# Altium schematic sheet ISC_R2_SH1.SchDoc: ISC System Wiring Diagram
size C; DrawnBy: Filiberto Clara; Engineer: Filiberto Clara; Organization: LIGO Laboratory; Address1: California Institute of Technology; Address2: Massachusetts Institute of Technology; SheetNumber: 13; SheetTotal: 39
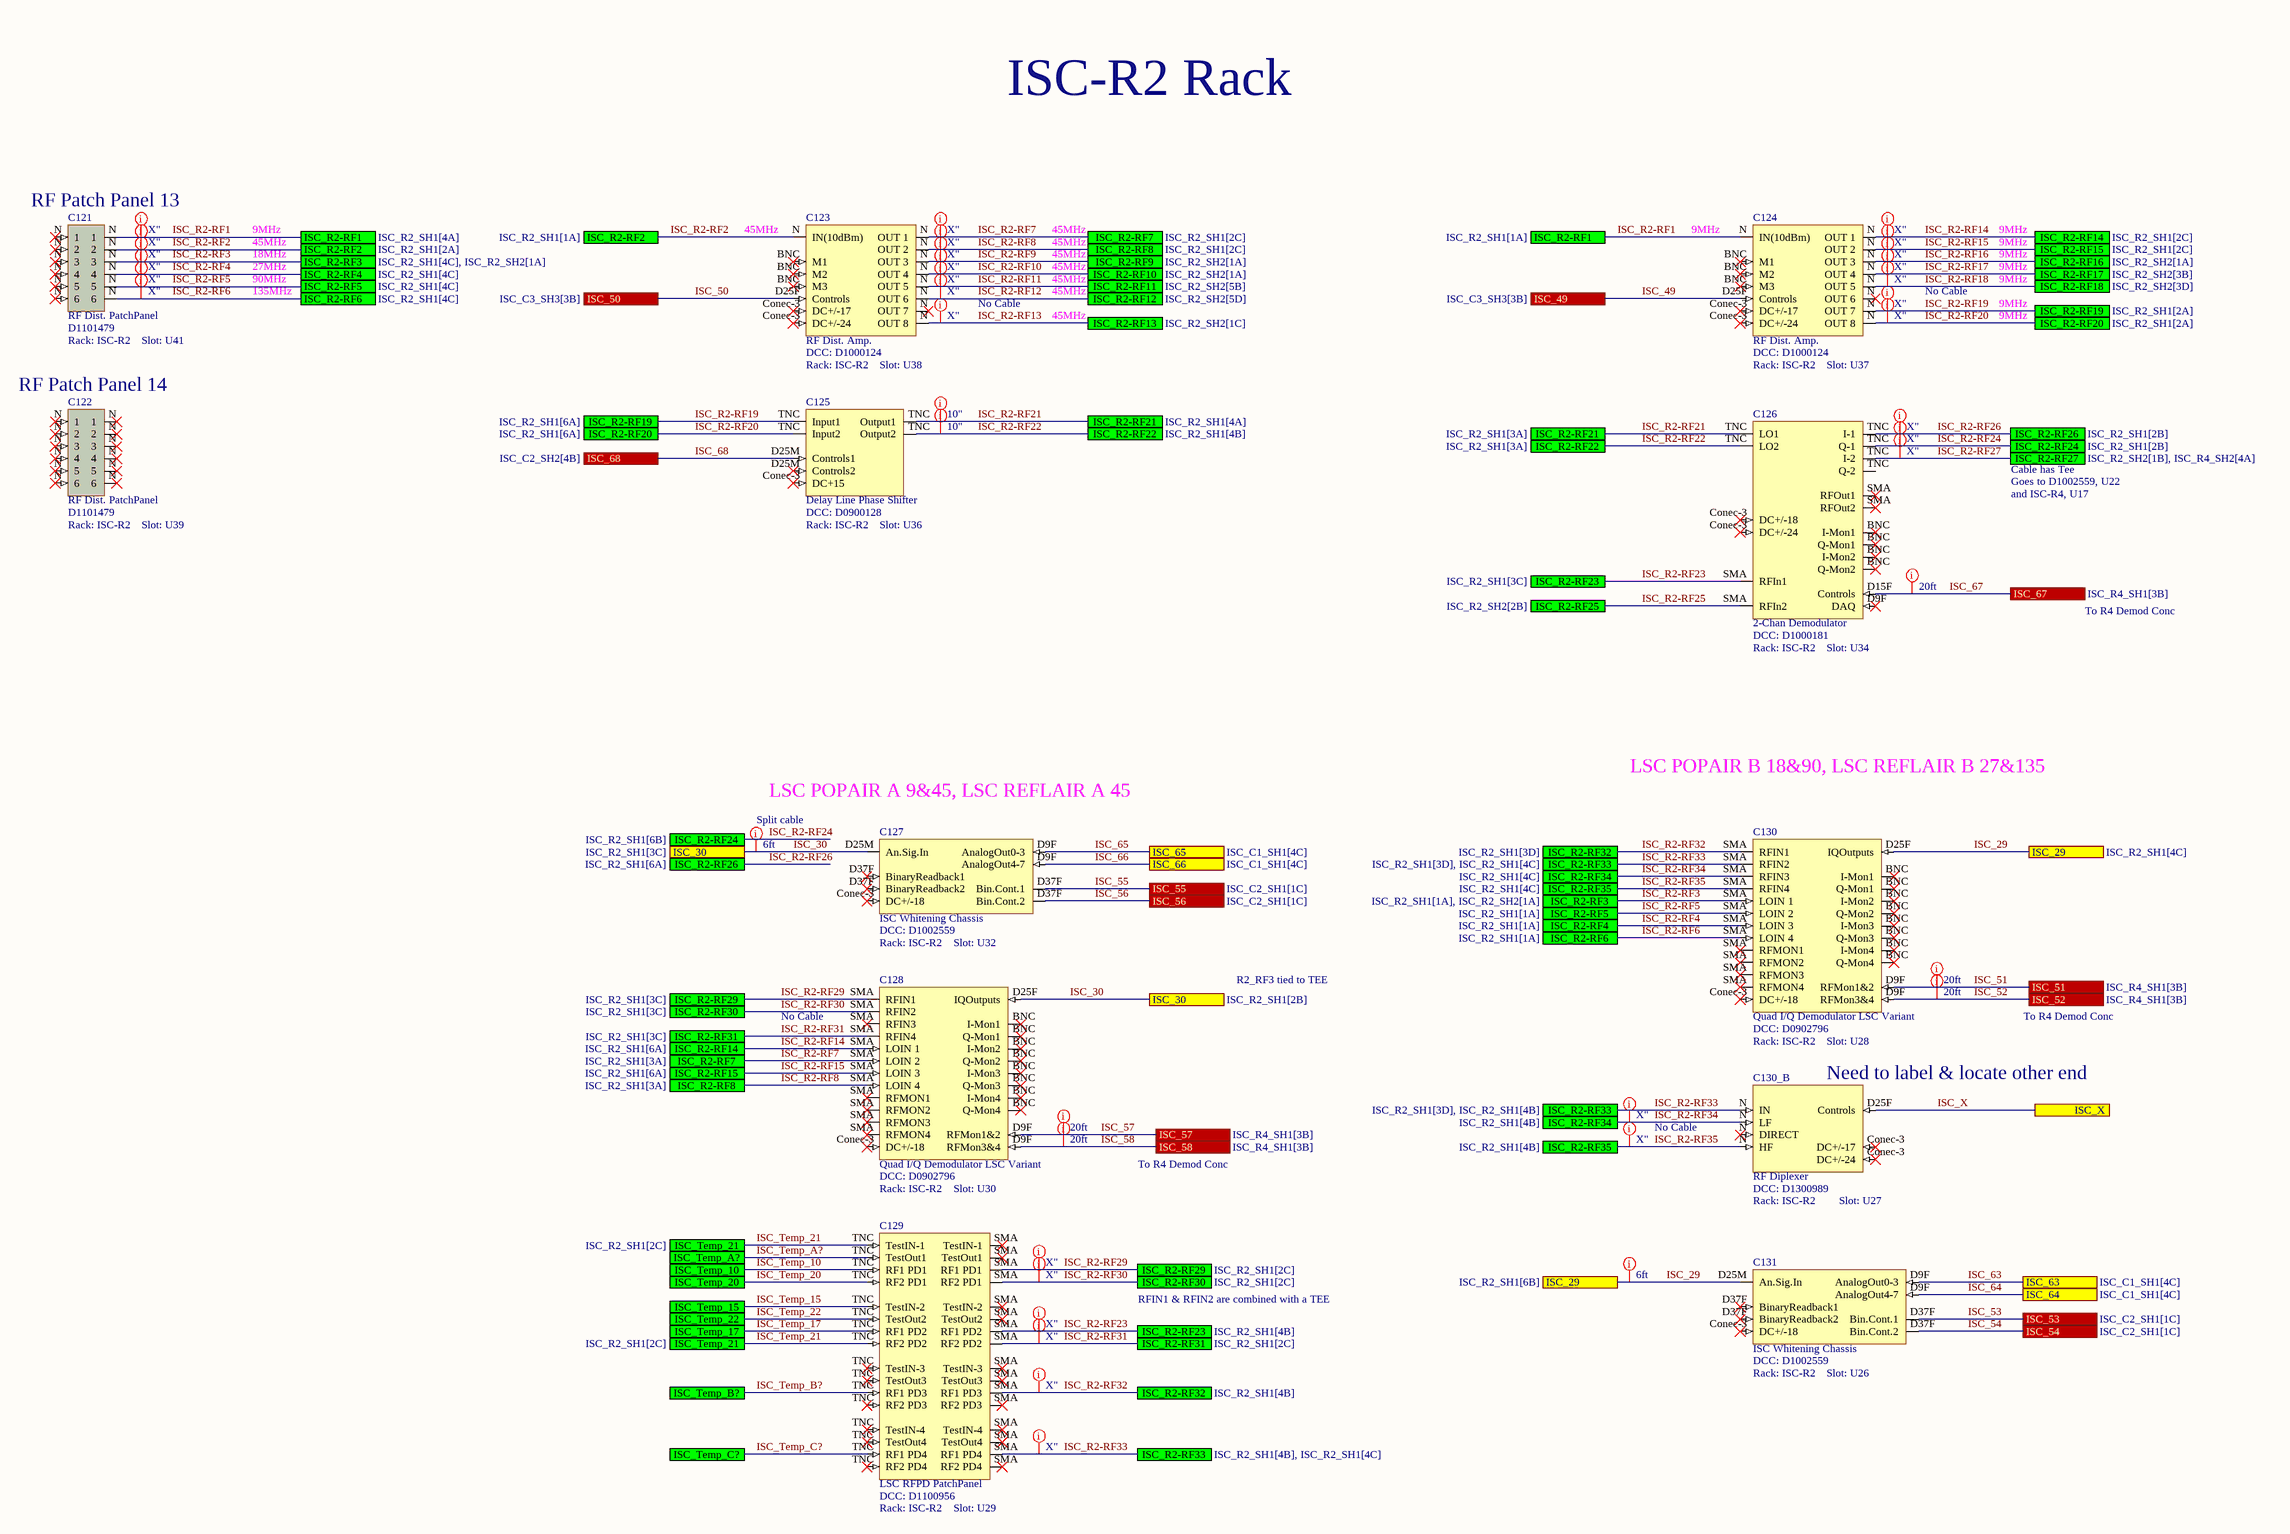
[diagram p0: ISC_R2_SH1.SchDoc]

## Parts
C121  RF Dist. PatchPanel  DCC: D1101479  Rack: ISC-R2  Slot: U41
C122  RF Dist. PatchPanel  DCC: D1101479  Rack: ISC-R2  Slot: U39
C123  RF Dist. Amp.  DCC: D1000124  Rack: ISC-R2  Slot: U38
C124  RF Dist. Amp.  DCC: D1000124  Rack: ISC-R2  Slot: U37
C125  Delay Line Phase Shifter  DCC: D0900128  Rack: ISC-R2  Slot: U36
C126  2-Chan Demodulator  DCC: D1000181  Rack: ISC-R2  Slot: U34
C127  ISC Whitening Chassis  DCC: D1002559  Rack: ISC-R2  Slot: U32
C128  Quad I/Q Demodulator LSC Variant  DCC: D0902796  Rack: ISC-R2  Slot: U30
C129  LSC RFPD PatchPanel  DCC: D1100956  Rack: ISC-R2  Slot: U29
C130  Quad I/Q Demodulator LSC Variant  DCC: D0902796  Rack: ISC-R2  Slot: U28
C130_B  RF Diplexer  DCC: D1300989  Rack: ISC-R2  Slot: U27
C131  ISC Whitening Chassis  DCC: D1002559  Rack: ISC-R2  Slot: U26

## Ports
ISC_29 (see ISC_R2_SH1[4C]), ISC_29 (see ISC_R2_SH1[6B]), ISC_30 (see ISC_R2_SH1[2B]), ISC_30 (see ISC_R2_SH1[3C]), ISC_49 (see ISC_C3_SH3[3B]), ISC_50 (see ISC_C3_SH3[3B]), ISC_51 (see ISC_R4_SH1[3B]), ISC_52 (see ISC_R4_SH1[3B]), ISC_53 (see ISC_C2_SH1[1C]), ISC_54 (see ISC_C2_SH1[1C]), ISC_55 (see ISC_C2_SH1[1C]), ISC_56 (see ISC_C2_SH1[1C]), ISC_57 (see ISC_R4_SH1[3B]), ISC_58 (see ISC_R4_SH1[3B]), ISC_63 (see ISC_C1_SH1[4C]), ISC_64 (see ISC_C1_SH1[4C]), ISC_65 (see ISC_C1_SH1[4C]), ISC_66 (see ISC_C1_SH1[4C]), ISC_67 (see ISC_R4_SH1[3B]), ISC_68 (see ISC_C2_SH2[4B]), ISC_R2-RF1 (see ISC_R2_SH1[1A]), ISC_R2-RF1 (see ISC_R2_SH1[4A]), ISC_R2-RF2 (see ISC_R2_SH1[1A]), ISC_R2-RF2 (see ISC_R2_SH1[2A]), ISC_R2-RF3 (see ISC_R2_SH1[1A], ISC_R2_SH2[1A]), ISC_R2-RF3 (see ISC_R2_SH1[4C], ISC_R2_SH2[1A]), ISC_R2-RF4 (see ISC_R2_SH1[1A]), ISC_R2-RF4 (see ISC_R2_SH1[4C]), ISC_R2-RF5 (see ISC_R2_SH1[1A]), ISC_R2-RF5 (see ISC_R2_SH1[4C]), ISC_R2-RF6 (see ISC_R2_SH1[1A]), ISC_R2-RF6 (see ISC_R2_SH1[4C]), ISC_R2-RF7 (see ISC_R2_SH1[2C]), ISC_R2-RF7 (see ISC_R2_SH1[3A]), ISC_R2-RF8 (see ISC_R2_SH1[2C]), ISC_R2-RF8 (see ISC_R2_SH1[3A]), ISC_R2-RF9 (see ISC_R2_SH2[1A]), ISC_R2-RF10 (see ISC_R2_SH2[1A]), ISC_R2-RF11 (see ISC_R2_SH2[5B]), ISC_R2-RF12 (see ISC_R2_SH2[5D]), ISC_R2-RF13 (see ISC_R2_SH2[1C]), ISC_R2-RF14 (see ISC_R2_SH1[2C]), ISC_R2-RF14 (see ISC_R2_SH1[6A]), ISC_R2-RF15 (see ISC_R2_SH1[2C]), ISC_R2-RF15 (see ISC_R2_SH1[6A]), ISC_R2-RF16 (see ISC_R2_SH2[1A]), ISC_R2-RF17 (see ISC_R2_SH2[3B]), ISC_R2-RF18 (see ISC_R2_SH2[3D]), ISC_R2-RF19 (see ISC_R2_SH1[2A]), ISC_R2-RF19 (see ISC_R2_SH1[6A]), ISC_R2-RF20 (see ISC_R2_SH1[2A]), ISC_R2-RF20 (see ISC_R2_SH1[6A]), ISC_R2-RF21 (see ISC_R2_SH1[3A]), ISC_R2-RF21 (see ISC_R2_SH1[4A]), ISC_R2-RF22 (see ISC_R2_SH1[3A]), ISC_R2-RF22 (see ISC_R2_SH1[4B]), ISC_R2-RF23 (see ISC_R2_SH1[3C]), ISC_R2-RF23 (see ISC_R2_SH1[4B]), ISC_R2-RF24 (see ISC_R2_SH1[2B]), ISC_R2-RF24 (see ISC_R2_SH1[6B]), ISC_R2-RF25 (see ISC_R2_SH2[2B]), ISC_R2-RF26 (see ISC_R2_SH1[2B]), ISC_R2-RF26 (see ISC_R2_SH1[6A]), ISC_R2-RF27 (see ISC_R2_SH2[1B], ISC_R4_SH2[4A]), ISC_R2-RF29 (see ISC_R2_SH1[2C]), ISC_R2-RF29 (see ISC_R2_SH1[3C]), ISC_R2-RF30 (see ISC_R2_SH1[2C]), ISC_R2-RF30 (see ISC_R2_SH1[3C]), ISC_R2-RF31 (see ISC_R2_SH1[2C]), ISC_R2-RF31 (see ISC_R2_SH1[3C]), ISC_R2-RF32 (see ISC_R2_SH1[3D]), ISC_R2-RF32 (see ISC_R2_SH1[4B]), ISC_R2-RF33 (see ISC_R2_SH1[3D], ISC_R2_SH1[4B]), ISC_R2-RF33 (see ISC_R2_SH1[3D], ISC_R2_SH1[4C]), ISC_R2-RF33 (see ISC_R2_SH1[4B], ISC_R2_SH1[4C]), ISC_R2-RF34 (see ISC_R2_SH1[4B]), ISC_R2-RF34 (see ISC_R2_SH1[4C]), ISC_R2-RF35 (see ISC_R2_SH1[4B]), ISC_R2-RF35 (see ISC_R2_SH1[4C]), ISC_Temp_10, ISC_Temp_15, ISC_Temp_17, ISC_Temp_20, ISC_Temp_21 (see ISC_R2_SH1[2C]), ISC_Temp_22, ISC_Temp_A?, ISC_Temp_B?, ISC_Temp_C?, ISC_X

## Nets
ISC_29: C130.D25F(IQOutputs) C131.D25M(An.Sig.In) ; port ISC_29
ISC_30: C127.D25M(An.Sig.In) C128.D25F(IQOutputs) ; port ISC_30
ISC_49: C124.D25F(Controls) ; port ISC_49
ISC_50: C123.D25F(Controls) ; port ISC_50
ISC_51: C130.D9F(RFMon1&2) ; port ISC_51
ISC_52: C130.D9F(RFMon3&4) ; port ISC_52
ISC_53: C131.D37F(BinaryReadback1) ; port ISC_53
ISC_54: C131.D37F(Bin.Cont.2) ; port ISC_54
ISC_55: C127.D37F(BinaryReadback1) ; port ISC_55
ISC_56: C127.D37F(Bin.Cont.2) ; port ISC_56
ISC_57: C128.D9F(RFMon1&2) ; port ISC_57
ISC_58: C128.D9F(RFMon3&4) ; port ISC_58
ISC_63: C131.D9F(AnalogOut0-3) ; port ISC_63
ISC_64: C131.D9F(AnalogOut4-7) ; port ISC_64
ISC_65: C127.D9F(AnalogOut0-3) ; port ISC_65
ISC_66: C127.D9F(AnalogOut4-7) ; port ISC_66
ISC_67: C126.D15F(Controls) ; port ISC_67
ISC_68: C125.D25M(Controls1) ; port ISC_68
ISC_R2-RF1: C121.N(1) C124.N(IN(10dBm)) ; port ISC_R2-RF1
ISC_R2-RF2: C121.N(2) C123.N(IN(10dBm)) ; port ISC_R2-RF2
ISC_R2-RF3: C121.N(3) C130.SMA(LOIN_1) ; port ISC_R2-RF3
ISC_R2-RF4: C121.N(4) C130.SMA(LOIN_3) ; port ISC_R2-RF4
ISC_R2-RF5: C121.N(5) C130.SMA(LOIN_2) ; port ISC_R2-RF5
ISC_R2-RF6: C121.N(6) C130.SMA(LOIN_4) ; port ISC_R2-RF6
ISC_R2-RF7: C123.N(OUT_1) C128.SMA(LOIN_2) ; port ISC_R2-RF7
ISC_R2-RF8: C123.N(OUT_2) C128.SMA(LOIN_4) ; port ISC_R2-RF8
ISC_R2-RF9: C123.N(OUT_3) ; port ISC_R2-RF9
ISC_R2-RF10: C123.N(OUT_4) ; port ISC_R2-RF10
ISC_R2-RF11: C123.N(OUT_5) ; port ISC_R2-RF11
ISC_R2-RF12: C123.N(OUT_6) ; port ISC_R2-RF12
ISC_R2-RF13: C123.N(OUT_8) ; port ISC_R2-RF13
ISC_R2-RF14: C124.N(OUT_1) C128.SMA(LOIN_1) ; port ISC_R2-RF14
ISC_R2-RF15: C124.N(OUT_2) C128.SMA(LOIN_3) ; port ISC_R2-RF15
ISC_R2-RF16: C124.N(OUT_3) ; port ISC_R2-RF16
ISC_R2-RF17: C124.N(OUT_4) ; port ISC_R2-RF17
ISC_R2-RF18: C124.N(OUT_5) ; port ISC_R2-RF18
ISC_R2-RF19: C124.N(OUT_7) C125.TNC(Input1) ; port ISC_R2-RF19
ISC_R2-RF20: C124.N(OUT_8) C125.TNC(Input2) ; port ISC_R2-RF20
ISC_R2-RF21: C125.TNC(Output1) C126.TNC(LO1) ; port ISC_R2-RF21
ISC_R2-RF22: C125.TNC(Output2) C126.TNC(LO2) ; port ISC_R2-RF22
ISC_R2-RF23: C126.SMA(RFOut1) C129.SMA(RF1_PD2) ; port ISC_R2-RF23
ISC_R2-RF24: C126.TNC(Q-1) ; port ISC_R2-RF24
ISC_R2-RF25: C126.SMA(RFIn2) ; port ISC_R2-RF25
ISC_R2-RF26: C126.TNC(I-1) ; port ISC_R2-RF26
ISC_R2-RF27: C126.TNC(I-2) ; port ISC_R2-RF27
ISC_R2-RF29: C128.SMA(RFIN1) C129.SMA(TestIN-1) ; port ISC_R2-RF29
ISC_R2-RF30: C128.SMA(RFIN2) C129.SMA(RF2_PD1) ; port ISC_R2-RF30
ISC_R2-RF31: C128.SMA(RFIN4) C129.SMA(RF2_PD2) ; port ISC_R2-RF31
ISC_R2-RF32: C129.SMA(RF1_PD3) C130.SMA(RFIN1) ; port ISC_R2-RF32
ISC_R2-RF33: C129.SMA(RF1_PD4) C130.SMA(RFIN2) C130_B.N(IN) ; port ISC_R2-RF33
ISC_R2-RF34: C130.SMA(RFIN3) C130_B.N(LF) ; port ISC_R2-RF34
ISC_R2-RF35: C130.SMA(RFIN4) C130_B.N(HF) ; port ISC_R2-RF35
ISC_Temp_10: C129.TNC(RF1_PD1) ; port ISC_Temp_10
ISC_Temp_15: C129.TNC(TestIN-2) ; port ISC_Temp_15
ISC_Temp_17: C129.TNC(RF1_PD2) ; port ISC_Temp_17
ISC_Temp_20: C129.TNC(RF2_PD1) ; port ISC_Temp_20
ISC_Temp_21: C129.TNC(TestIN-1) ; port ISC_Temp_21
ISC_Temp_22: C129.TNC(TestOut2) ; port ISC_Temp_22
ISC_Temp_A?: C129.TNC(TestOut1) ; port ISC_Temp_A?
ISC_Temp_B?: C129.TNC(RF1_PD3) ; port ISC_Temp_B?
ISC_Temp_C?: C129.TNC(RF1_PD4) ; port ISC_Temp_C?
ISC_X: C130_B.D25F(Controls) ; port ISC_X

Not connected (* = marked no-connect by the designer): C122 N(1)*; C123 BNC(M1)* Conec-3(DC+/-17)*; C124 BNC(M1)* Conec-3(DC+/-17)*; C125 Conec-3(DC+15)*; C126 BNC(I-Mon1)* Conec-3(DC+/-18)* D9F(DAQ)*; C127 Conec-3(DC+/-18)*; C128 BNC(I-Mon1)* Conec-3(DC+/-18)*; C130 BNC(I-Mon1)* Conec-3(DC+/-18)*; C130_B Conec-3(DC+/-17)*; C131 Conec-3(DC+/-18)*

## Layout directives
Length: X": ISC_R2-RF1, ISC_R2-RF2, ISC_R2-RF3, ISC_R2-RF4, ISC_R2-RF5, ISC_R2-RF6, ISC_R2-RF7, ISC_R2-RF8, ISC_R2-RF9, ISC_R2-RF10, ISC_R2-RF11, ISC_R2-RF12, ISC_R2-RF13, ISC_R2-RF14, ISC_R2-RF15, ISC_R2-RF16, ISC_R2-RF17, ISC_R2-RF18, ISC_R2-RF19, ISC_R2-RF20, ISC_R2-RF23, ISC_R2-RF24, ISC_R2-RF26, ISC_R2-RF27, ISC_R2-RF29, ISC_R2-RF30, ISC_R2-RF31, ISC_R2-RF32, ISC_R2-RF33, ISC_R2-RF34, ISC_R2-RF35
Length: 20ft: ISC_51, ISC_52, ISC_57, ISC_58, ISC_67
Length: 10": ISC_R2-RF21, ISC_R2-RF22
Length: 6ft: ISC_29, ISC_30

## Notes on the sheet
- ISC-R2 Rack
- (near C121) RF Patch Panel 13
- 9MHz
- 45MHz
- (near C123) 45MHz
- (near C124) 9MHz
- 18MHz
- 27MHz
- 90MHz
- 135MHz
- No Cable
- (near C122) RF Patch Panel 14
- Cable has Tee
- Goes to D1002559, U22
- and ISC-R4, U17
- To R4 Demod Conc
- LSC POPAIR A 9&45, LSC REFLAIR A 45
- LSC POPAIR B 18&90, LSC REFLAIR B 27&135
- Split cable
- R2_RF3 tied to TEE
- (near C130_B) Need to label & locate other end
- RFIN1 & RFIN2 are combined with a TEE

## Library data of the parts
C121 C122 = RF Dist. PatchPanel: Serial: Sxxxxxxx; System: ISC
C123 C124 = RF Distribution Amplifier: Serial: Sxxxxxxx; System: ISC
C125 = DelayLinePhaseShifter: Serial: Sxxxxxxx; System: ISC
C126 = 2-Chan Demod: Serial: Sxxxxxxx; System: ISC
C127 C131 = ISC Whitening: Serial: Sxxxxxxx
C128 C130 = QuadIQdemod_LSC: Serial: Sxxxxxxx; System: ISC
C129 = LSC RFPD PatchPanel: Serial: Sxxxxxxx; System: ISC
C130_B = RF Diplexer: Serial: Sxxxxxxx; System: ISC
